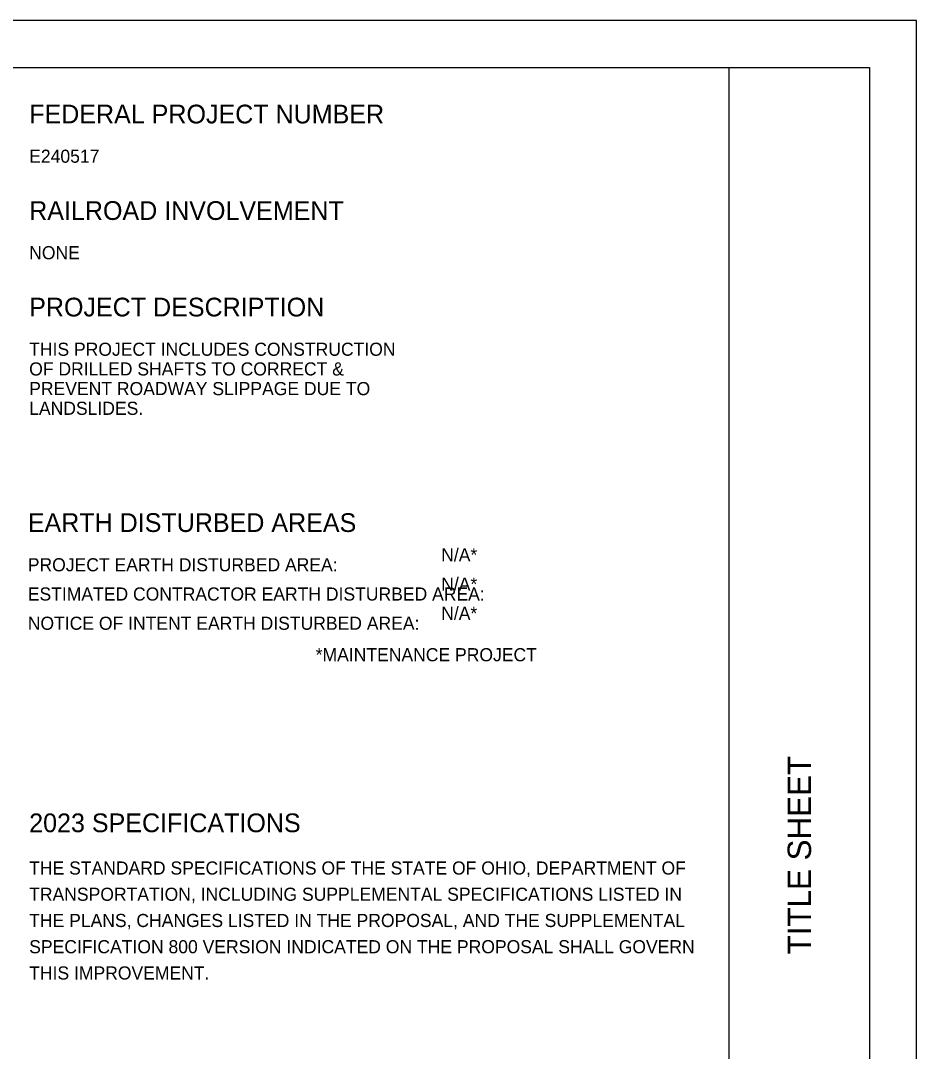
# Model space of a CAD drawing. Extents: x -21.1 to 50.3, y 0 to 22.1.
# Drawn here: x 24.44 to 34, y 11 to 22 of the extents above; entities that cross this region are included whole.
import ezdxf

# ---------------------------------------------------------------- set-up
doc = ezdxf.new("R2010")
doc.units = 0
for name, color, linetype in [('SH_Border', 7, 'Continuous'), ('SH_Cut_Line', 7, 'Continuous'), ('SH_Data', 7, 'Continuous'), ('SH_Text', 7, 'Continuous')]:
    doc.layers.add(name, color=color, linetype=linetype)

msp = doc.modelspace()

# ---------------------------------------------------------------- linework, layer by layer
at = {"layer": 'SH_Border'}
msp.add_line((32, 0.5), (32, 21.5), dxfattribs=at)
msp.add_lwpolyline([(1.5, 21.5), (33.5, 21.5), (33.5, 0.5), (1.5, 0.5)], close=True, dxfattribs=at)
at = {"layer": 'SH_Cut_Line'}
msp.add_lwpolyline([(0, 0), (34, 0), (34, 22), (0, 22)], close=True, dxfattribs=at)

# ---------------------------------------------------------------- texts
at = {"layer": 'SH_Data'}
msp.add_text('TITLE SHEET', height=0.25, rotation=90, dxfattribs=at).set_placement((32.875, 12.035))
at = {"layer": 'SH_Text'}
for s, height, p in [('FEDERAL PROJECT NUMBER', 0.2, (24.528, 20.903)), ('E240517', 0.14, (24.528, 20.483)), ('RAILROAD INVOLVEMENT', 0.2, (24.528, 19.873)), ('NONE', 0.14, (24.528, 19.453)), ('PROJECT DESCRIPTION', 0.2, (24.528, 18.843)), ('THIS PROJECT INCLUDES CONSTRUCTION ', 0.14, (24.528, 18.423)), ('OF DRILLED SHAFTS TO CORRECT & ', 0.14, (24.528, 18.213)), ('PREVENT ROADWAY SLIPPAGE DUE TO ', 0.14, (24.528, 18.003)), ('LANDSLIDES. ', 0.14, (24.528, 17.793)), ('EARTH DISTURBED AREAS', 0.2, (24.513, 16.543)), ('N/A*', 0.14, (28.927, 16.229)), ('PROJECT EARTH DISTURBED AREA:', 0.14, (24.513, 16.123)), ('N/A*', 0.14, (28.927, 15.917)), ('ESTIMATED CONTRACTOR EARTH DISTURBED AREA:', 0.14, (24.513, 15.811)), ('N/A*', 0.14, (28.927, 15.605)), ('NOTICE OF INTENT EARTH DISTURBED AREA:', 0.14, (24.513, 15.499)), ('*MAINTENANCE PROJECT', 0.14, (27.587, 15.163)), ('2023 SPECIFICATIONS', 0.2, (24.528, 13.339)), ('THE STANDARD SPECIFICATIONS OF THE STATE OF OHIO, DEPARTMENT OF', 0.14, (24.528, 12.887)), ('TRANSPORTATION, INCLUDING SUPPLEMENTAL SPECIFICATIONS LISTED IN', 0.14, (24.528, 12.607)), ('THE PLANS, CHANGES LISTED IN THE PROPOSAL, AND THE SUPPLEMENTAL', 0.14, (24.528, 12.327)), ('SPECIFICATION 800 VERSION INDICATED ON THE PROPOSAL SHALL GOVERN', 0.14, (24.528, 12.047)), ('THIS IMPROVEMENT.', 0.14, (24.528, 11.767))]:
    msp.add_text(s, height=height, dxfattribs=at).set_placement(p)

doc.saveas('drawing.dxf')
